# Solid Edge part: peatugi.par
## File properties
Author: Georg
Template: Iso Part.par
Last saved by: Kalle
Revision: 4
Application: Solid Edge
Accuracy: 0,990
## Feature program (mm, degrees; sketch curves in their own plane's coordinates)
sketch for "unnamed Protrusion 1" plane through (0, 0, 0) normal (0, 0, 1) x-axis (1, 0, 0)
  line (-11.5, -6.5) -> (11.5, -6.5)
  line (11.5, -6.5) -> (11.5, 6.5)
  line (11.5, 6.5) -> (-11.5, 6.5)
  line (-11.5, 6.5) -> (-11.5, -6.5)
  dimension (linear) = 11.5
  dimension (linear) = 11.5
extrude "unnamed Protrusion 1" add finite 10 along +normal
sketch for "ExtrudedCutout_1" plane through (11.5, 0, 5) normal (1, 0, 0) x-axis (0, 1, 0)
  line (-1.5526, 5.6383) -> (-6.5, 1)
  line (-1.5526, 5.6383) -> (1.5526, 5.6383)
  line (1.5526, 5.6383) -> (6.5, 1)
extrude "ExtrudedCutout_1" cut finite 89.8793 along -normal
sketch for "ExtrudedCutout_2" plane through (0, -6.5, 3.0868) normal (0, -1, 0) x-axis (1, 0, 0)
  line (-6.5, 6.9132) -> (-11.5, -0.0868)
extrude "ExtrudedCutout_2" cut finite 68.4073 along -normal
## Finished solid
Body 1: solid body, 9 faces, 21 edges, 14 vertices.
  Faces by surface: plane 9
  Edges by curve: line 21
Bounding box of the edges (mm): 23.000 x 13.000 x 10.000, from (-11.5, -6.5, 0) to (11.5, 6.5, 10).
Planar faces by outward normal: +x 1, +y 1, +z 1, -x 1, -y 1, -z 1, oblique 3
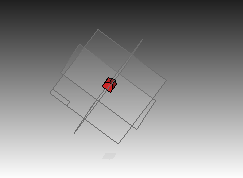
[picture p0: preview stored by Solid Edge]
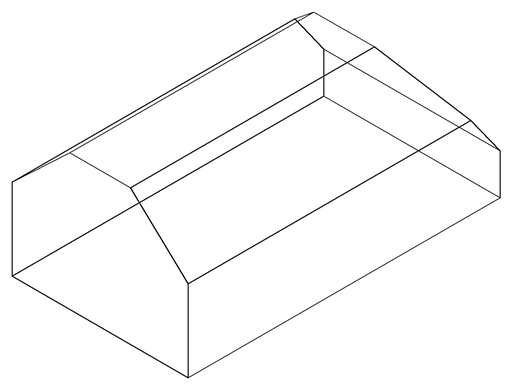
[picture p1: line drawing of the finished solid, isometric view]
